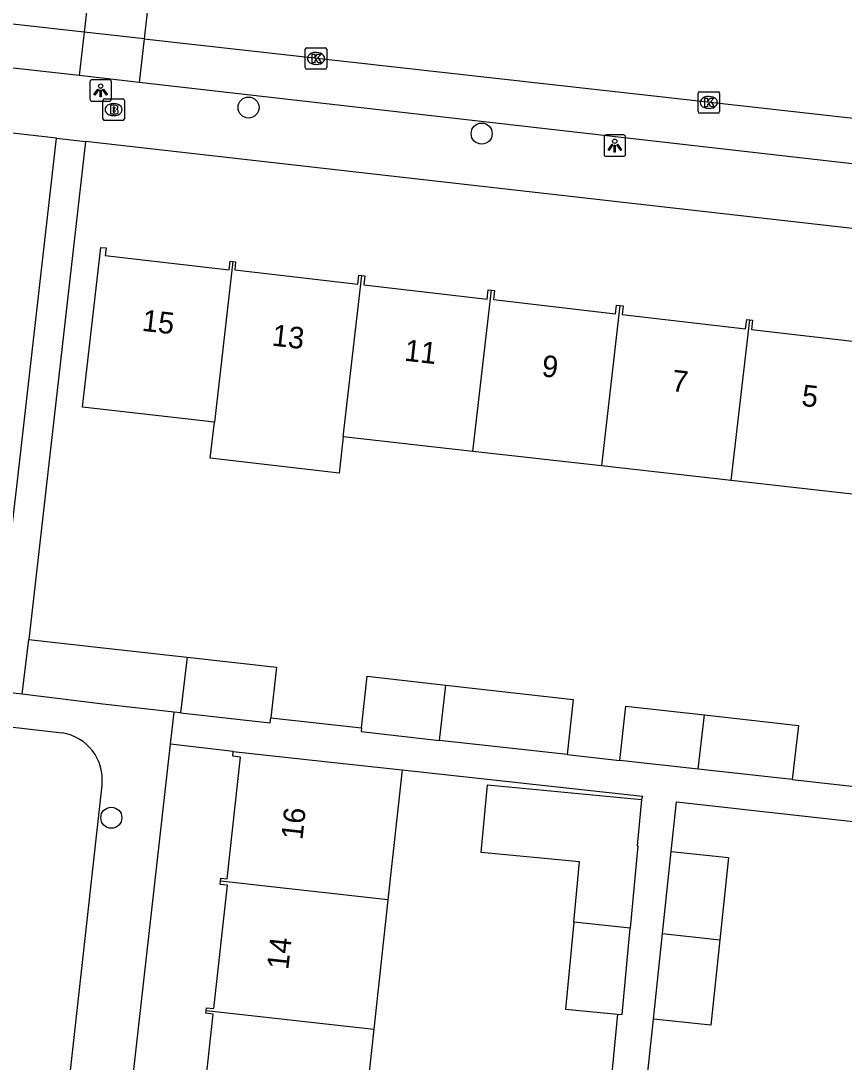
# Model space of a CAD drawing. Extents: x 161928 to 163055, y 386475 to 387428.
# Drawn here: x 162121.59 to 162159.87, y 386596.21 to 386644.64 of the extents above; entities that cross this region are included whole.
import ezdxf

# ---------------------------------------------------------------- set-up
doc = ezdxf.new("R2010")
doc.units = 0
for name, color, linetype in [('IMGEO_Boom', 7, 'Continuous'), ('IMGEO_Brandkraan', 7, 'Continuous'), ('IMGEO_Kolk', 7, 'Continuous'), ('IMGEO_Lichtpunt', 7, 'Continuous'), ('IMGEO_Pand', 7, 'Continuous'), ('IMGEO_Pand_nummerreeks', 7, 'Continuous'), ('IMGEO_Parkeervlak_open', 7, 'Continuous'), ('IMGEO_Rijbaan_lokaal_open', 7, 'Continuous'), ('IMGEO_Voetpad_open', 7, 'Continuous')]:
    doc.layers.add(name, color=color, linetype=linetype)

msp = doc.modelspace()

# ---------------------------------------------------------------- linework, layer by layer
at = {"layer": 'IMGEO_Boom'}
for centre in [(162132.179, 386640.606), (162143.018, 386639.393), (162125.799, 386607.575)]:
    msp.add_circle(centre, 0.489, dxfattribs=at)
at = {"layer": 'IMGEO_Brandkraan'}
for p, q in [((162125.406, 386640.084), (162125.406, 386640.936)), ((162125.481, 386641.01), (162126.333, 386641.01)), ((162125.894, 386640.79), (162125.919, 386640.79)), ((162126.407, 386640.936), (162126.407, 386640.084)), ((162125.917, 386640.23), (162125.892, 386640.23)), ((162126.333, 386640.01), (162125.481, 386640.01))]:
    msp.add_line(p, q, dxfattribs=at)
for points in [[(162125.406, 386640.084), (162125.406, 386640.936)], [(162125.481, 386641.01), (162126.333, 386641.01)], [(162125.754, 386640.71), (162125.754, 386640.31), (162125.967, 386640.31)], [(162125.985, 386640.71), (162125.754, 386640.71)], [(162126.407, 386640.936), (162126.407, 386640.084)], [(162125.933, 386640.629), (162125.879, 386640.629), (162125.879, 386640.553)], [(162125.879, 386640.553), (162125.932, 386640.553)], [(162125.941, 386640.477), (162125.879, 386640.477), (162125.879, 386640.396)], [(162125.879, 386640.396), (162125.941, 386640.396)], [(162126.333, 386640.01), (162125.481, 386640.01)]]:
    msp.add_lwpolyline(points, dxfattribs=at)
for centre, radius, start, end in [((162125.483, 386640.934), 0.0765, 91.552, 178.448), ((162125.483, 386640.934), 0.0765, 91.552, 178.448), ((162125.989, 386640.565), 0.145, 59.4692, 91.5367), ((162126.014, 386640.612), 0.0922, 285.5137, 58.1501), ((162126.331, 386640.934), 0.0765, 1.552, 88.448), ((162126.331, 386640.934), 0.0765, 1.552, 88.448), ((162125.934, 386640.591), 0.0379, 267.8285, 90.9355), ((162125.942, 386640.436), 0.0404, 269.8759, 90.5077), ((162125.973, 386640.561), 0.251, 268.6676, 293.5347), ((162126.019, 386640.42), 0.105, 301.3115, 78.989), ((162125.483, 386640.086), 0.0765, 181.552, 268.448), ((162125.483, 386640.086), 0.0765, 181.552, 268.448), ((162126.331, 386640.086), 0.0765, 271.552, 358.448), ((162126.331, 386640.086), 0.0765, 271.552, 358.448)]:
    msp.add_arc(centre, radius, start, end, dxfattribs=at)
for centre, major_axis, ratio, start_param, end_param in [((162125.893, 386640.51), (-0.387, 0.002), 0.722429, 4.712389, 7.853982), ((162125.918, 386640.51), (-0.39, 0.002), 0.717154, 1.570796, 4.712389)]:
    msp.add_ellipse(centre, major_axis=major_axis, ratio=ratio, start_param=start_param, end_param=end_param, dxfattribs=at)
at = {"layer": 'IMGEO_Kolk'}
for p, q in [((162134.815, 386642.462), (162134.815, 386643.314)), ((162134.89, 386643.388), (162135.742, 386643.388)), ((162135.303, 386643.168), (162135.328, 386643.168)), ((162135.816, 386643.314), (162135.816, 386642.462)), ((162135.326, 386642.608), (162135.301, 386642.608)), ((162135.742, 386642.388), (162134.89, 386642.388)), ((162153.078, 386640.416), (162153.078, 386641.268)), ((162153.153, 386641.342), (162154.005, 386641.342)), ((162154.079, 386641.268), (162154.079, 386640.416)), ((162153.566, 386641.122), (162153.591, 386641.122)), ((162154.005, 386640.342), (162153.153, 386640.342)), ((162153.589, 386640.562), (162153.564, 386640.562))]:
    msp.add_line(p, q, dxfattribs=at)
for points in [[(162134.815, 386642.462), (162134.815, 386643.314)], [(162134.89, 386643.388), (162135.742, 386643.388)], [(162135.816, 386643.314), (162135.816, 386642.462)], [(162135.136, 386643.088), (162135.259, 386643.088), (162135.259, 386642.937), (162135.389, 386643.088), (162135.553, 386643.088), (162135.407, 386642.937), (162135.56, 386642.688), (162135.408, 386642.688), (162135.323, 386642.852), (162135.259, 386642.785), (162135.259, 386642.688), (162135.136, 386642.688), (162135.136, 386643.088)], [(162135.742, 386642.388), (162134.89, 386642.388)], [(162153.078, 386640.416), (162153.078, 386641.268)], [(162153.153, 386641.342), (162154.005, 386641.342)], [(162154.079, 386641.268), (162154.079, 386640.416)], [(162153.399, 386641.042), (162153.522, 386641.042), (162153.522, 386640.891), (162153.652, 386641.042), (162153.816, 386641.042), (162153.67, 386640.891), (162153.823, 386640.642), (162153.671, 386640.642), (162153.586, 386640.806), (162153.522, 386640.739), (162153.522, 386640.642), (162153.399, 386640.642), (162153.399, 386641.042)], [(162154.005, 386640.342), (162153.153, 386640.342)]]:
    msp.add_lwpolyline(points, dxfattribs=at)
for centre, start, end in [((162134.892, 386643.312), 91.552, 178.448), ((162134.892, 386643.312), 91.552, 178.448), ((162135.74, 386643.312), 1.552, 88.448), ((162135.74, 386643.312), 1.552, 88.448), ((162134.892, 386642.464), 181.552, 268.448), ((162134.892, 386642.464), 181.552, 268.448), ((162135.74, 386642.464), 271.552, 358.448), ((162135.74, 386642.464), 271.552, 358.448), ((162153.155, 386641.266), 91.552, 178.448), ((162153.155, 386641.266), 91.552, 178.448), ((162154.003, 386641.266), 1.552, 88.448), ((162154.003, 386641.266), 1.552, 88.448), ((162153.155, 386640.418), 181.552, 268.448), ((162153.155, 386640.418), 181.552, 268.448), ((162154.003, 386640.418), 271.552, 358.448), ((162154.003, 386640.418), 271.552, 358.448)]:
    msp.add_arc(centre, 0.0765, start, end, dxfattribs=at)
for centre, major_axis, ratio, start_param, end_param in [((162135.302, 386642.888), (-0.387, 0.002), 0.722429, 4.712389, 7.853982), ((162135.327, 386642.888), (-0.39, 0.002), 0.717154, 1.570796, 4.712389), ((162153.565, 386640.842), (-0.387, 0.002), 0.722429, 4.712389, 7.853982), ((162153.59, 386640.842), (-0.39, 0.002), 0.717154, 1.570796, 4.712389)]:
    msp.add_ellipse(centre, major_axis=major_axis, ratio=ratio, start_param=start_param, end_param=end_param, dxfattribs=at)
at = {"layer": 'IMGEO_Lichtpunt'}
for p, q in [((162124.806, 386641.804), (162124.806, 386640.997)), ((162124.806, 386641.804), (162124.806, 386640.997)), ((162125.708, 386641.899), (162124.9, 386641.899)), ((162125.708, 386641.899), (162124.9, 386641.899)), ((162125.802, 386640.997), (162125.802, 386641.804)), ((162125.802, 386640.997), (162125.802, 386641.804)), ((162124.9, 386640.903), (162125.708, 386640.903)), ((162124.9, 386640.903), (162125.708, 386640.903)), ((162148.708, 386639.24), (162148.708, 386638.433)), ((162148.708, 386639.24), (162148.708, 386638.433)), ((162149.61, 386639.335), (162148.802, 386639.335)), ((162149.61, 386639.335), (162148.802, 386639.335)), ((162149.704, 386638.433), (162149.704, 386639.24)), ((162149.704, 386638.433), (162149.704, 386639.24)), ((162148.802, 386638.339), (162149.61, 386638.339)), ((162148.802, 386638.339), (162149.61, 386638.339))]:
    msp.add_line(p, q, dxfattribs=at)
for points in [[(162125.18, 386641.468), (162125.219, 386641.44), (162125.031, 386641.178), (162124.993, 386641.205), (162125.18, 386641.468)], [(162125.282, 386641.42), (162125.329, 386641.42), (162125.329, 386641.098), (162125.282, 386641.098), (162125.282, 386641.42)], [(162125.392, 386641.44), (162125.43, 386641.467), (162125.617, 386641.205), (162125.578, 386641.177), (162125.392, 386641.44)], [(162149.082, 386638.904), (162149.121, 386638.876), (162148.933, 386638.614), (162148.895, 386638.641), (162149.082, 386638.904)], [(162149.184, 386638.856), (162149.231, 386638.856), (162149.231, 386638.534), (162149.184, 386638.534), (162149.184, 386638.856)], [(162149.294, 386638.876), (162149.332, 386638.903), (162149.519, 386638.641), (162149.48, 386638.613), (162149.294, 386638.876)]]:
    msp.add_lwpolyline(points, dxfattribs=at)
for centre in [(162125.305, 386641.602), (162149.207, 386639.038)]:
    msp.add_circle(centre, 0.0994, dxfattribs=at)
for centre, start, end in [((162124.9, 386641.804), 90, 180), ((162124.9, 386641.804), 90, 180), ((162125.708, 386641.804), 0, 90), ((162125.708, 386641.804), 0, 90), ((162124.9, 386640.997), 180, 270), ((162124.9, 386640.997), 180, 270), ((162125.708, 386640.997), 270, 0), ((162125.708, 386640.997), 270, 360), ((162148.802, 386639.24), 90, 180), ((162148.802, 386639.24), 90, 180), ((162149.61, 386639.24), 0, 90), ((162149.61, 386639.24), 0, 90), ((162148.802, 386638.433), 180, 270), ((162148.802, 386638.433), 180, 270), ((162149.61, 386638.433), 270, 0), ((162149.61, 386638.433), 270, 360)]:
    msp.add_arc(centre, 0.0946, start, end, dxfattribs=at)
at = {"layer": 'IMGEO_Pand'}
for points in [[(162130.593, 386625.97), (162124.455, 386626.664), (162125.313, 386634.104), (162125.554, 386634.076), (162125.513, 386633.718), (162131.278, 386633.053), (162131.324, 386633.454), (162131.452, 386633.44)], [(162131.452, 386633.44), (162130.593, 386625.97)], [(162131.452, 386633.44), (162131.58, 386633.425), (162131.538, 386633.058), (162137.259, 386632.398), (162137.305, 386632.804), (162137.448, 386632.788)], [(162136.586, 386625.293), (162137.448, 386632.788)], [(162137.448, 386632.788), (162137.588, 386632.772), (162137.54, 386632.356), (162143.273, 386631.695), (162143.323, 386632.135), (162143.472, 386632.118)], [(162142.608, 386624.613), (162143.472, 386632.118)], [(162143.472, 386632.118), (162143.62, 386632.101), (162143.57, 386631.672), (162149.245, 386631.018), (162149.292, 386631.419), (162149.442, 386631.402)], [(162149.442, 386631.402), (162148.583, 386623.937)], [(162149.442, 386631.402), (162149.593, 386631.384), (162149.546, 386630.973), (162155.29, 386630.311), (162155.341, 386630.755), (162155.478, 386630.739)], [(162154.617, 386623.256), (162155.478, 386630.739)], [(162155.478, 386630.739), (162155.614, 386630.724), (162155.563, 386630.286), (162161.329, 386629.621), (162161.382, 386630.083), (162161.525, 386630.067)], [(162136.586, 386625.293), (162136.392, 386623.605), (162130.4, 386624.294), (162130.593, 386625.97)], [(162142.608, 386624.613), (162136.586, 386625.293)], [(162148.583, 386623.937), (162142.608, 386624.613)], [(162154.617, 386623.256), (162148.583, 386623.937)], [(162160.662, 386622.573), (162154.617, 386623.256)], [(162121.662, 386613.315), (162121.966, 386615.861)], [(162121.966, 386615.861), (162125.693, 386615.447), (162129.321, 386615.04)], [(162129.321, 386615.04), (162129.021, 386612.449)], [(162129.321, 386615.04), (162133.478, 386614.574), (162133.214, 386612.225)], [(162137.427, 386611.752), (162137.696, 386614.152), (162141.354, 386613.742)], [(162141.057, 386611.174), (162141.354, 386613.742)], [(162141.354, 386613.742), (162147.275, 386613.078), (162146.987, 386610.509)], [(162128.717, 386612.483), (162125.402, 386612.855), (162121.662, 386613.315)], [(162149.437, 386610.244), (162149.72, 386612.766), (162153.377, 386612.355)], [(162129.021, 386612.449), (162128.717, 386612.483)], [(162129.021, 386612.449), (162133.187, 386611.982), (162133.214, 386612.225)], [(162153.085, 386609.835), (162153.377, 386612.355)], [(162153.377, 386612.355), (162157.742, 386611.866), (162157.459, 386609.345)], [(162137.427, 386611.752), (162137.408, 386611.583), (162141.057, 386611.174)], [(162146.987, 386610.509), (162141.057, 386611.174)], [(162130.878, 386604.618), (162130.893, 386604.761), (162131.186, 386604.729), (162131.807, 386610.399), (162131.448, 386610.438), (162131.472, 386610.662)], [(162131.472, 386610.662), (162136.443, 386610.117), (162139.322, 386609.802)], [(162153.085, 386609.835), (162149.437, 386610.244)], [(162139.322, 386609.802), (162138.66, 386603.762)], [(162157.459, 386609.345), (162153.085, 386609.835)], [(162147.302, 386602.72), (162147.565, 386605.523), (162142.995, 386605.951), (162143.29, 386609.098), (162150.451, 386608.427)], [(162150.451, 386608.427), (162150.248, 386606.267), (162150.278, 386606.264), (162149.919, 386602.433)], [(162151.43, 386602.193), (162151.832, 386606.003)], [(162151.832, 386606.003), (162154.488, 386605.723), (162154.084, 386601.896)], [(162130.208, 386598.602), (162130.222, 386598.732), (162130.567, 386598.695), (162131.196, 386604.438), (162130.862, 386604.474), (162130.878, 386604.618)], [(162138.66, 386603.762), (162130.878, 386604.618)], [(162138.66, 386603.762), (162138.002, 386597.745)], [(162147.302, 386602.72), (162146.922, 386598.665), (162149.329, 386598.439)], [(162149.919, 386602.433), (162147.302, 386602.72)], [(162149.329, 386598.439), (162149.544, 386598.419), (162149.919, 386602.433)], [(162151.008, 386598.203), (162151.43, 386602.193)], [(162151.43, 386602.193), (162154.084, 386601.896)], [(162154.084, 386601.896), (162153.665, 386597.923), (162151.008, 386598.203)], [(162129.534, 386592.64), (162129.55, 386592.784), (162129.918, 386592.744), (162130.542, 386598.439), (162130.194, 386598.477), (162130.208, 386598.602)], [(162130.208, 386598.602), (162138.002, 386597.745)], [(162138.002, 386597.745), (162137.349, 386591.781)]]:
    msp.add_lwpolyline(points, dxfattribs=at)
at = {"layer": 'IMGEO_Parkeervlak_open'}
for points in [[(162124.536, 386644.116), (162124.305, 386642.089)], [(162127.319, 386643.804), (162127.088, 386641.777)]]:
    msp.add_lwpolyline(points, dxfattribs=at)
at = {"layer": 'IMGEO_Rijbaan_lokaal_open'}
for points in [[(162124.536, 386644.116), (162076.681, 386649.471)], [(162125.103, 386649.091), (162124.536, 386644.116)], [(162127.886, 386648.779), (162127.319, 386643.804)], [(162127.319, 386643.804), (162124.536, 386644.116)], [(162127.319, 386643.804), (162174.153, 386638.563)]]:
    msp.add_lwpolyline(points, dxfattribs=at)
at = {"layer": 'IMGEO_Voetpad_open'}
for points in [[(162124.305, 386642.089), (162080.121, 386647.031), (162080.012, 386647.052), (162079.777, 386647.114), (162079.548, 386647.196), (162079.327, 386647.298), (162079.117, 386647.42), (162078.918, 386647.56), (162078.732, 386647.717), (162078.562, 386647.89), (162078.407, 386648.078), (162078.27, 386648.279), (162078.12, 386648.489), (162077.953, 386648.684), (162077.768, 386648.864), (162077.569, 386649.026), (162077.355, 386649.17), (162077.13, 386649.295), (162076.894, 386649.398), (162076.681, 386649.471)], [(162123.254, 386639.182), (162083.251, 386643.731), (162074.703, 386644.498)], [(162127.088, 386641.777), (162124.305, 386642.089)], [(162170.223, 386636.883), (162169.752, 386636.9), (162127.088, 386641.777)], [(162120.277, 386613.481), (162121.412, 386622.981), (162123.254, 386639.182)], [(162124.601, 386639.029), (162121.966, 386615.861)], [(162123.254, 386639.182), (162124.601, 386639.029)], [(162174.012, 386633.555), (162174.002, 386633.43), (162168.309, 386634.058), (162124.601, 386639.029)], [(162121.662, 386613.315), (162120.277, 386613.481)], [(162128.549, 386610.991), (162128.717, 386612.483)], [(162133.214, 386612.225), (162137.427, 386611.752)], [(162119.329, 386612), (162123.51, 386611.519)], [(162123.113, 386562.703), (162128.549, 386610.991)], [(162131.472, 386610.662), (162128.549, 386610.991)], [(162146.987, 386610.509), (162149.437, 386610.244)], [(162139.322, 386609.802), (162150.495, 386608.579), (162150.451, 386608.427)], [(162157.459, 386609.345), (162161.465, 386608.906)], [(162125.366, 386609.092), (162121.902, 386577.926)], [(162151.832, 386606.003), (162152.076, 386608.314), (162163.338, 386607.058)], [(162149.329, 386598.439), (162148.936, 386594.251)], [(162150.564, 386593.998), (162151.008, 386598.203)]]:
    msp.add_lwpolyline(points, dxfattribs=at)
msp.add_arc((162123.17, 386609.336), 2.21, 353.6702, 81.1422, dxfattribs=at)

# ---------------------------------------------------------------- texts
at = {"layer": 'IMGEO_Pand_nummerreeks'}
for s, rotation, p in [('15', 353.5056, (162127.191, 386630.225)), ('13', 353.5056, (162133.233, 386629.537)), ('11', 353.5056, (162139.389, 386628.837)), ('9', 353.5056, (162145.775, 386628.11)), ('7', 353.5056, (162151.817, 386627.422)), ('5', 353.5056, (162157.859, 386626.734)), ('16', 83.7749, (162134.683, 386606.517)), ('14', 83.7749, (162134.024, 386600.479))]:
    msp.add_text(s, height=1, rotation=rotation, dxfattribs=at).set_placement(p)

doc.saveas('drawing.dxf')
